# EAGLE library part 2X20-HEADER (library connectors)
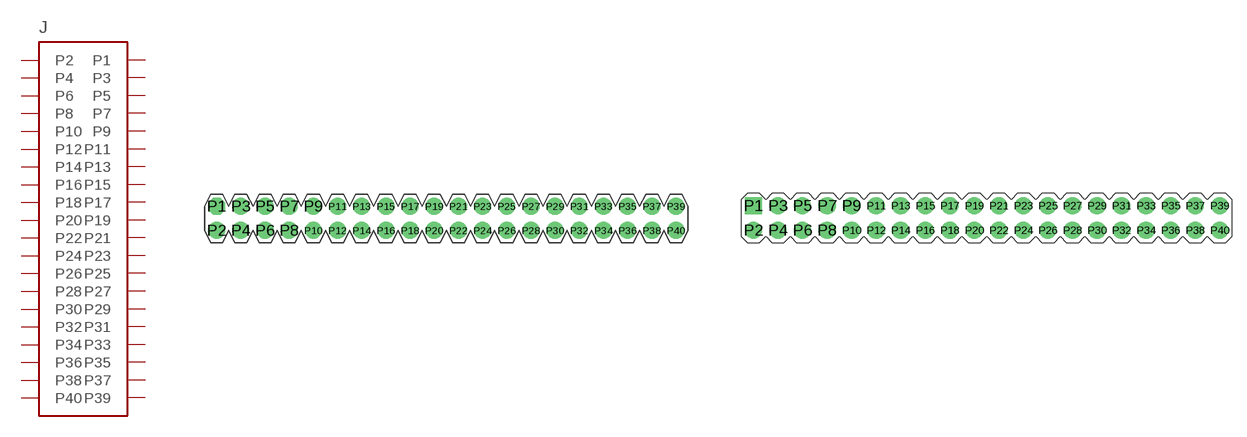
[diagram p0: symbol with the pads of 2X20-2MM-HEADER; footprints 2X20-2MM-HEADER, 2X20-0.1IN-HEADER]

Designator prefix J

## 2X20-HEADER2MM-SMD  [2X20-2MM-HEADER]
P1  P1  pas
P2  P2  pas
P3  P3  pas
P4  P4  pas
P5  P5  pas
P6  P6  pas
P7  P7  pas
P8  P8  pas
P9  P9  pas
P10  P10  pas
P11  P11  pas
P12  P12  pas
P13  P13  pas
P14  P14  pas
P15  P15  pas
P16  P16  pas
P17  P17  pas
P18  P18  pas
P19  P19  pas
P20  P20  pas
P21  P21  pas
P22  P22  pas
P23  P23  pas
P24  P24  pas
P25  P25  pas
P26  P26  pas
P27  P27  pas
P28  P28  pas
P29  P29  pas
P30  P30  pas
P31  P31  pas
P32  P32  pas
P33  P33  pas
P34  P34  pas
P35  P35  pas
P36  P36  pas
P37  P37  pas
P38  P38  pas
P39  P39  pas
P40  P40  pas

## 2X20-HEADER0.1IN  [2X20-0.1IN-HEADER]
Pads as for 2X20-2MM-HEADER

## Footprint 2X20-2MM-HEADER (pad centres in mm)
drill 0.85 pad 1.4 octagon: P1 -19,1
drill 0.85 pad 1.4 round: P2 -19,-1; P3 -17,1; P4 -17,-1; P5 -15,1; P6 -15,-1; P7 -13,1; P8 -13,-1; P9 -11,1; P10 -11,-1; P11 -9,1; P12 -9,-1; P13 -7,1; P14 -7,-1; P15 -5,1; P16 -5,-1; P17 -3,1; P18 -3,-1; P19 -1,1; P20 -1,-1; P21 1,1; P22 1,-1; P23 3,1; P24 3,-1; P25 5,1; P26 5,-1; P27 7,1; P28 7,-1; P29 9,1; P30 9,-1; P31 11,1; P32 11,-1; P33 13,1; P34 13,-1; P35 15,1; P36 15,-1; P37 17,1; P38 17,-1; P39 19,1; P40 19,-1

## Footprint 2X20-0.1IN-HEADER (pad centres in mm)
drill 1.05 pad 1.778 square: P1 -24.13,1.27
drill 1.05 pad 1.778 round: P2 -24.13,-1.27; P3 -21.59,1.27; P4 -21.59,-1.27; P5 -19.05,1.27; P6 -19.05,-1.27; P7 -16.51,1.27; P8 -16.51,-1.27; P9 -13.97,1.27; P10 -13.97,-1.27; P11 -11.43,1.27; P12 -11.43,-1.27; P13 -8.89,1.27; P14 -8.89,-1.27; P15 -6.35,1.27; P16 -6.35,-1.27; P17 -3.81,1.27; P18 -3.81,-1.27; P19 -1.27,1.27; P20 -1.27,-1.27; P21 1.27,1.27; P22 1.27,-1.27; P23 3.81,1.27; P24 3.81,-1.27; P25 6.35,1.27; P26 6.35,-1.27; P27 8.89,1.27; P28 8.89,-1.27; P29 11.43,1.27; P30 11.43,-1.27; P31 13.97,1.27; P32 13.97,-1.27; P33 16.51,1.27; P34 16.51,-1.27; P35 19.05,1.27; P36 19.05,-1.27; P37 21.59,1.27; P38 21.59,-1.27; P39 24.13,1.27; P40 24.13,-1.27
